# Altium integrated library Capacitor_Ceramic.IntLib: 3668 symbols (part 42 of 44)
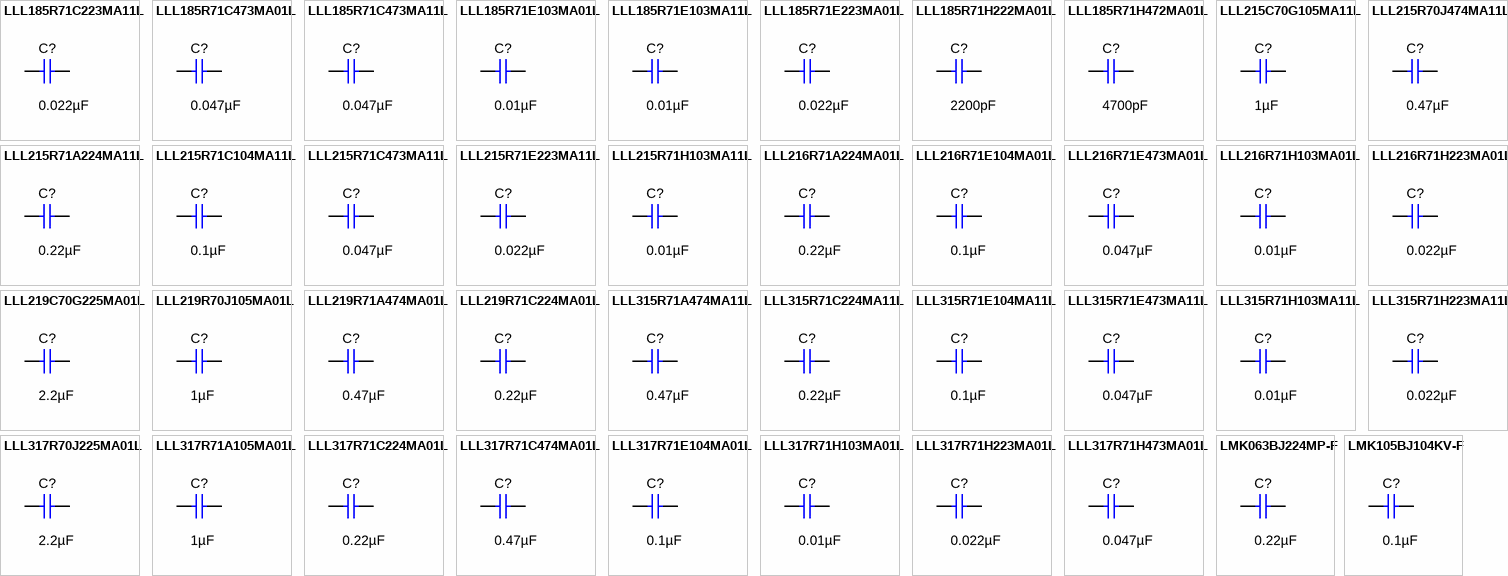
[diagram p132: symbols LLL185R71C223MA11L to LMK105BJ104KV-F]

## LLL216R71A224MA01L
designator C?  ValueDisplayed: 0.22µF  (hidden comment: LLL216R71A224MA01L)
CAP, CERM, 0.22 µF, 10 V,+/- 20%, X7R, 0508; Manufacturer: MuRata; Polarized: N; CompType: Capacitor; Value: 0.22uF; U/M: EA; Cap_F: 0.00000022; Tolerance_%: 20; VDC_V: 10; Value2: 10V; TaMin_C: -55; TaMax_C: 125; Cap_Case: 0508; SizeArea_mm2: 2.5; SizeAreaWB_mm2: 6.75; SizeX_mm: 1.25; SizeY_mm: 2; SizeZ_mm: 1; AEC Category: Q200
signal-integrity model Cap
simulation model Cap
footprint 0508
pins: 1, 2

## LLL216R71E104MA01L
designator C?  ValueDisplayed: 0.1µF  (hidden comment: LLL216R71E104MA01L)
CAP, CERM, 0.1 µF, 25 V,+/- 20%, X7R, 0508; Manufacturer: MuRata; Polarized: N; CompType: Capacitor; Value: 0.1uF; U/M: EA; Cap_F: 0.0000001; Tolerance_%: 20; VDC_V: 25; Value2: 25V; TaMin_C: -55; TaMax_C: 125; Cap_Case: 0508; SizeArea_mm2: 2.5; SizeAreaWB_mm2: 6.75; SizeX_mm: 1.25; SizeY_mm: 2; SizeZ_mm: 1; AEC Category: Q200
signal-integrity model Cap
simulation model Cap
footprint 0508
pins: 1, 2

## LLL216R71E473MA01L
designator C?  ValueDisplayed: 0.047µF  (hidden comment: LLL216R71E473MA01L)
CAP, CERM, 0.047 µF, 25 V,+/- 20%, X7R, 0508; Manufacturer: MuRata; Polarized: N; CompType: Capacitor; Value: 0.047uF; U/M: EA; Cap_F: 0.000000047; Tolerance_%: 20; VDC_V: 25; Value2: 25V; TaMin_C: -55; TaMax_C: 125; Cap_Case: 0508; SizeArea_mm2: 2.5; SizeAreaWB_mm2: 6.75; SizeX_mm: 1.25; SizeY_mm: 2; SizeZ_mm: 1; AEC Category: Q200
signal-integrity model Cap
simulation model Cap
footprint 0508
pins: 1, 2

## LLL216R71H103MA01L
designator C?  ValueDisplayed: 0.01µF  (hidden comment: LLL216R71H103MA01L)
CAP, CERM, 0.01 µF, 50 V,+/- 20%, X7R, 0508; Manufacturer: MuRata; Polarized: N; CompType: Capacitor; Value: 0.01uF; U/M: EA; Cap_F: 0.00000001; Tolerance_%: 20; VDC_V: 50; Value2: 50V; TaMin_C: -55; TaMax_C: 125; Cap_Case: 0508; SizeArea_mm2: 2.5; SizeAreaWB_mm2: 6.75; SizeX_mm: 1.25; SizeY_mm: 2; SizeZ_mm: 1; AEC Category: Q200
signal-integrity model Cap
simulation model Cap
footprint 0508
pins: 1, 2

## LLL216R71H223MA01L
designator C?  ValueDisplayed: 0.022µF  (hidden comment: LLL216R71H223MA01L)
CAP, CERM, 0.022 µF, 50 V,+/- 20%, X7R, 0508; Manufacturer: MuRata; Polarized: N; CompType: Capacitor; Value: 0.022uF; U/M: EA; Cap_F: 0.000000022; Tolerance_%: 20; VDC_V: 50; Value2: 50V; TaMin_C: -55; TaMax_C: 125; Cap_Case: 0508; SizeArea_mm2: 2.5; SizeAreaWB_mm2: 6.75; SizeX_mm: 1.25; SizeY_mm: 2; SizeZ_mm: 1; AEC Category: Q200
signal-integrity model Cap
simulation model Cap
footprint 0508
pins: 1, 2

## LLL219C70G225MA01L
designator C?  ValueDisplayed: 2.2µF  (hidden comment: LLL219C70G225MA01L)
CAP, CERM, 2.2 µF, 4 V,+/- 20%, X7S, 0508; Manufacturer: MuRata; Polarized: N; CompType: Capacitor; Value: 2.2uF; U/M: EA; Cap_F: 0.0000022; Tolerance_%: 20; VDC_V: 4; Value2: 4V; TaMin_C: -55; TaMax_C: 125; Cap_Case: 0508; SizeArea_mm2: 2.5; SizeAreaWB_mm2: 6.75; SizeX_mm: 1.25; SizeY_mm: 2; SizeZ_mm: 1; AEC Category: Q200
signal-integrity model Cap
simulation model Cap
footprint 0508
pins: 1, 2

## LLL219R70J105MA01L
designator C?  ValueDisplayed: 1µF  (hidden comment: LLL219R70J105MA01L)
CAP, CERM, 1 µF, 6.3 V,+/- 20%, X7R, 0508; Manufacturer: MuRata; Polarized: N; CompType: Capacitor; Value: 1uF; U/M: EA; Cap_F: 0.000001; Tolerance_%: 20; VDC_V: 6.3; Value2: 6.3V; TaMin_C: -55; TaMax_C: 125; Cap_Case: 0508; SizeArea_mm2: 2.5; SizeAreaWB_mm2: 6.75; SizeX_mm: 1.25; SizeY_mm: 2; SizeZ_mm: 1; AEC Category: Q200
signal-integrity model Cap
simulation model Cap
footprint 0508
pins: 1, 2

## LLL219R71A474MA01L
designator C?  ValueDisplayed: 0.47µF  (hidden comment: LLL219R71A474MA01L)
CAP, CERM, 0.47 µF, 10 V,+/- 20%, X7R, 0508; Manufacturer: MuRata; Polarized: N; CompType: Capacitor; Value: 0.47uF; U/M: EA; Cap_F: 0.00000047; Tolerance_%: 20; VDC_V: 10; Value2: 10V; TaMin_C: -55; TaMax_C: 125; Cap_Case: 0508; SizeArea_mm2: 2.5; SizeAreaWB_mm2: 6.75; SizeX_mm: 1.25; SizeY_mm: 2; SizeZ_mm: 1; AEC Category: Q200
signal-integrity model Cap
simulation model Cap
footprint 0508
pins: 1, 2

## LLL219R71C224MA01L
designator C?  ValueDisplayed: 0.22µF  (hidden comment: LLL219R71C224MA01L)
CAP, CERM, 0.22 µF, 16 V,+/- 20%, X7R, 0508; Manufacturer: MuRata; Polarized: N; CompType: Capacitor; Value: 0.22uF; U/M: EA; Cap_F: 0.00000022; Tolerance_%: 20; VDC_V: 16; Value2: 16V; TaMin_C: -55; TaMax_C: 125; Cap_Case: 0508; SizeArea_mm2: 2.5; SizeAreaWB_mm2: 6.75; SizeX_mm: 1.25; SizeY_mm: 2; SizeZ_mm: 1; AEC Category: Q200
signal-integrity model Cap
simulation model Cap
footprint 0508
pins: 1, 2

## LLL315R71A474MA11L
designator C?  ValueDisplayed: 0.47µF  (hidden comment: LLL315R71A474MA11L)
CAP, CERM, 0.47 µF, 10 V,+/- 20%, X7R, 0612; Manufacturer: MuRata; Polarized: N; CompType: Capacitor; Value: 0.47uF; U/M: EA; Cap_F: 0.00000047; Tolerance_%: 20; VDC_V: 10; Value2: 10V; TaMin_C: -55; TaMax_C: 125; Cap_Case: 0612; SizeArea_mm2: 5.12; SizeAreaWB_mm2: 10.92; SizeX_mm: 1.6; SizeY_mm: 3.2; SizeZ_mm: 0.85; AEC Category: Q200
signal-integrity model Cap
simulation model Cap
footprint 0612
pins: 1, 2

## LLL315R71C224MA11L
designator C?  ValueDisplayed: 0.22µF  (hidden comment: LLL315R71C224MA11L)
CAP, CERM, 0.22 µF, 16 V,+/- 20%, X7R, 0612; Manufacturer: MuRata; Polarized: N; CompType: Capacitor; Value: 0.22uF; U/M: EA; Cap_F: 0.00000022; Tolerance_%: 20; VDC_V: 16; Value2: 16V; TaMin_C: -55; TaMax_C: 125; Cap_Case: 0612; SizeArea_mm2: 5.12; SizeAreaWB_mm2: 10.92; SizeX_mm: 1.6; SizeY_mm: 3.2; SizeZ_mm: 0.85; AEC Category: Q200
signal-integrity model Cap
simulation model Cap
footprint 0612
pins: 1, 2

## LLL315R71E104MA11L
designator C?  ValueDisplayed: 0.1µF  (hidden comment: LLL315R71E104MA11L)
CAP, CERM, 0.1 µF, 25 V,+/- 20%, X7R, 0612; Manufacturer: MuRata; Polarized: N; CompType: Capacitor; Value: 0.1uF; U/M: EA; Cap_F: 0.0000001; Tolerance_%: 20; VDC_V: 25; Value2: 25V; TaMin_C: -55; TaMax_C: 125; Cap_Case: 0612; SizeArea_mm2: 5.12; SizeAreaWB_mm2: 10.92; SizeX_mm: 1.6; SizeY_mm: 3.2; SizeZ_mm: 0.85; AEC Category: Q200
signal-integrity model Cap
simulation model Cap
footprint 0612
pins: 1, 2

## LLL315R71E473MA11L
designator C?  ValueDisplayed: 0.047µF  (hidden comment: LLL315R71E473MA11L)
CAP, CERM, 0.047 µF, 25 V,+/- 20%, X7R, 0612; Manufacturer: MuRata; Polarized: N; CompType: Capacitor; Value: 0.047uF; U/M: EA; Cap_F: 0.000000047; Tolerance_%: 20; VDC_V: 25; Value2: 25V; TaMin_C: -55; TaMax_C: 125; Cap_Case: 0612; SizeArea_mm2: 5.12; SizeAreaWB_mm2: 10.92; SizeX_mm: 1.6; SizeY_mm: 3.2; SizeZ_mm: 0.85; AEC Category: Q200
signal-integrity model Cap
simulation model Cap
footprint 0612
pins: 1, 2

## LLL315R71H103MA11L
designator C?  ValueDisplayed: 0.01µF  (hidden comment: LLL315R71H103MA11L)
CAP, CERM, 0.01 µF, 50 V,+/- 20%, X7R, 0612; Manufacturer: MuRata; Polarized: N; CompType: Capacitor; Value: 0.01uF; U/M: EA; Cap_F: 0.00000001; Tolerance_%: 20; VDC_V: 50; Value2: 50V; TaMin_C: -55; TaMax_C: 125; Cap_Case: 0612; SizeArea_mm2: 5.12; SizeAreaWB_mm2: 10.92; SizeX_mm: 1.6; SizeY_mm: 3.2; SizeZ_mm: 0.85; AEC Category: Q200
signal-integrity model Cap
simulation model Cap
footprint 0612
pins: 1, 2

## LLL315R71H223MA11L
designator C?  ValueDisplayed: 0.022µF  (hidden comment: LLL315R71H223MA11L)
CAP, CERM, 0.022 µF, 50 V,+/- 20%, X7R, 0612; Manufacturer: MuRata; Polarized: N; CompType: Capacitor; Value: 0.022uF; U/M: EA; Cap_F: 0.000000022; Tolerance_%: 20; VDC_V: 50; Value2: 50V; TaMin_C: -55; TaMax_C: 125; Cap_Case: 0612; SizeArea_mm2: 5.12; SizeAreaWB_mm2: 10.92; SizeX_mm: 1.6; SizeY_mm: 3.2; SizeZ_mm: 0.85; AEC Category: Q200
signal-integrity model Cap
simulation model Cap
footprint 0612
pins: 1, 2

## LLL317R70J225MA01L
designator C?  ValueDisplayed: 2.2µF  (hidden comment: LLL317R70J225MA01L)
CAP, CERM, 2.2 µF, 6.3 V,+/- 20%, X7R, 0612; Manufacturer: MuRata; Polarized: N; CompType: Capacitor; Value: 2.2uF; U/M: EA; Cap_F: 0.0000022; Tolerance_%: 20; VDC_V: 6.3; Value2: 6.3V; TaMin_C: -55; TaMax_C: 125; Cap_Case: 0612; SizeArea_mm2: 5.12; SizeAreaWB_mm2: 10.92; SizeX_mm: 1.6; SizeY_mm: 3.2; SizeZ_mm: 0.85; AEC Category: Q200
signal-integrity model Cap
simulation model Cap
footprint 0612
pins: 1, 2

## LLL317R71A105MA01L
designator C?  ValueDisplayed: 1µF  (hidden comment: LLL317R71A105MA01L)
CAP, CERM, 1 µF, 10 V,+/- 20%, X7R, 0612; Manufacturer: MuRata; Polarized: N; CompType: Capacitor; Value: 1uF; U/M: EA; Cap_F: 0.000001; Tolerance_%: 20; VDC_V: 10; Value2: 10V; TaMin_C: -55; TaMax_C: 125; Cap_Case: 0612; SizeArea_mm2: 5.12; SizeAreaWB_mm2: 10.92; SizeX_mm: 1.6; SizeY_mm: 3.2; SizeZ_mm: 0.85; AEC Category: Q200
signal-integrity model Cap
simulation model Cap
footprint 0612
pins: 1, 2

## LLL317R71C224MA01L
designator C?  ValueDisplayed: 0.22µF  (hidden comment: LLL317R71C224MA01L)
CAP, CERM, 0.22 µF, 16 V,+/- 20%, X7R, 0612; Manufacturer: MuRata; Polarized: N; CompType: Capacitor; Value: 0.22uF; U/M: EA; Cap_F: 0.00000022; Tolerance_%: 20; VDC_V: 16; Value2: 16V; TaMin_C: -55; TaMax_C: 125; Cap_Case: 0612; SizeArea_mm2: 5.12; SizeAreaWB_mm2: 10.92; SizeX_mm: 1.6; SizeY_mm: 3.2; SizeZ_mm: 0.85; AEC Category: Q200
signal-integrity model Cap
simulation model Cap
footprint 0612
pins: 1, 2

## LLL317R71C474MA01L
designator C?  ValueDisplayed: 0.47µF  (hidden comment: LLL317R71C474MA01L)
CAP, CERM, 0.47 µF, 16 V,+/- 20%, X7R, 0612; Manufacturer: MuRata; Polarized: N; CompType: Capacitor; Value: 0.47uF; U/M: EA; Cap_F: 0.00000047; Tolerance_%: 20; VDC_V: 16; Value2: 16V; TaMin_C: -55; TaMax_C: 125; Cap_Case: 0612; SizeArea_mm2: 5.12; SizeAreaWB_mm2: 10.92; SizeX_mm: 1.6; SizeY_mm: 3.2; SizeZ_mm: 0.85; AEC Category: Q200
signal-integrity model Cap
simulation model Cap
footprint 0612
pins: 1, 2

## LLL317R71E104MA01L
designator C?  ValueDisplayed: 0.1µF  (hidden comment: LLL317R71E104MA01L)
CAP, CERM, 0.1 µF, 25 V,+/- 20%, X7R, 0612; Manufacturer: MuRata; Polarized: N; CompType: Capacitor; Value: 0.1uF; U/M: EA; Cap_F: 0.0000001; Tolerance_%: 20; VDC_V: 25; Value2: 25V; TaMin_C: -55; TaMax_C: 125; Cap_Case: 0612; SizeArea_mm2: 5.12; SizeAreaWB_mm2: 10.92; SizeX_mm: 1.6; SizeY_mm: 3.2; SizeZ_mm: 0.85; AEC Category: Q200
signal-integrity model Cap
simulation model Cap
footprint 0612
pins: 1, 2

## LLL317R71H103MA01L
designator C?  ValueDisplayed: 0.01µF  (hidden comment: LLL317R71H103MA01L)
CAP, CERM, 0.01 µF, 50 V,+/- 20%, X7R, 0612; Manufacturer: MuRata; Polarized: N; CompType: Capacitor; Value: 0.01uF; U/M: EA; Cap_F: 0.00000001; Tolerance_%: 20; VDC_V: 50; Value2: 50V; TaMin_C: -55; TaMax_C: 125; Cap_Case: 0612; SizeArea_mm2: 5.12; SizeAreaWB_mm2: 10.92; SizeX_mm: 1.6; SizeY_mm: 3.2; SizeZ_mm: 0.85; AEC Category: Q200
signal-integrity model Cap
simulation model Cap
footprint 0612
pins: 1, 2

## LLL317R71H223MA01L
designator C?  ValueDisplayed: 0.022µF  (hidden comment: LLL317R71H223MA01L)
CAP, CERM, 0.022 µF, 50 V,+/- 20%, X7R, 0612; Manufacturer: MuRata; Polarized: N; CompType: Capacitor; Value: 0.022uF; U/M: EA; Cap_F: 0.000000022; Tolerance_%: 20; VDC_V: 50; Value2: 50V; TaMin_C: -55; TaMax_C: 125; Cap_Case: 0612; SizeArea_mm2: 5.12; SizeAreaWB_mm2: 10.92; SizeX_mm: 1.6; SizeY_mm: 3.2; SizeZ_mm: 0.85; AEC Category: Q200
signal-integrity model Cap
simulation model Cap
footprint 0612
pins: 1, 2

## LLL317R71H473MA01L
designator C?  ValueDisplayed: 0.047µF  (hidden comment: LLL317R71H473MA01L)
CAP, CERM, 0.047 µF, 50 V,+/- 20%, X7R, 0612; Manufacturer: MuRata; Polarized: N; CompType: Capacitor; Value: 0.047uF; U/M: EA; Cap_F: 0.000000047; Tolerance_%: 20; VDC_V: 50; Value2: 50V; TaMin_C: -55; TaMax_C: 125; Cap_Case: 0612; SizeArea_mm2: 5.12; SizeAreaWB_mm2: 10.92; SizeX_mm: 1.6; SizeY_mm: 3.2; SizeZ_mm: 0.85; AEC Category: Q200
signal-integrity model Cap
simulation model Cap
footprint 0612
pins: 1, 2

## LMK063BJ224MP-F
designator C?  ValueDisplayed: 0.22µF  (hidden comment: LMK063BJ224MP-F)
CAP, CERM, 0.22 µF, 10 V,+/- 20%, X5R, 0201; Manufacturer: Taiyo Yuden; Polarized: N; CompType: Capacitor; Value: 0.22uF; U/M: EA; Cap_F: 0.00000022; Tolerance_%: 20; VDC_V: 10; Value2: 10V; TaMin_C: -55; TaMax_C: 85; Cap_Case: 0201; SizeArea_mm2: 0.18; SizeAreaWB_mm2: 2.08; SizeX_mm: 0.6; SizeY_mm: 0.3; SizeZ_mm: 0.33; AEC Category: Q200; Green_Lifecycle: Active; Green_REACh: Passed
signal-integrity model Cap
simulation model Cap
footprint 0201_033
footprint 0201_033M
footprint 0201_033L
pins: 1, 2

## LMK105BJ104KV-F
designator C?  ValueDisplayed: 0.1µF  (hidden comment: LMK105BJ104KV-F)
CAP, CERM, 0.1 µF, 10 V,+/- 10%, X5R, 0402; Manufacturer: Taiyo Yuden; Polarized: N; CompType: Capacitor; Value: 0.1uF; U/M: EA; Cap_F: 0.0000001; Tolerance_%: 10; Value2: 10V; TaMin_C: -55; TaMax_C: 85; Cap_Case: 0402; SizeArea_mm2: 0.5; SizeAreaWB_mm2: 3; SizeX_mm: 1; SizeZ_mm: 0.6; AEC Category: Q200; Green_Lifecycle: Active; Green_REACh: Passed
signal-integrity model Cap
simulation model Cap
footprint 0402
footprint 0402M
footprint 0402L
footprint 0402S
pins: 1, 2

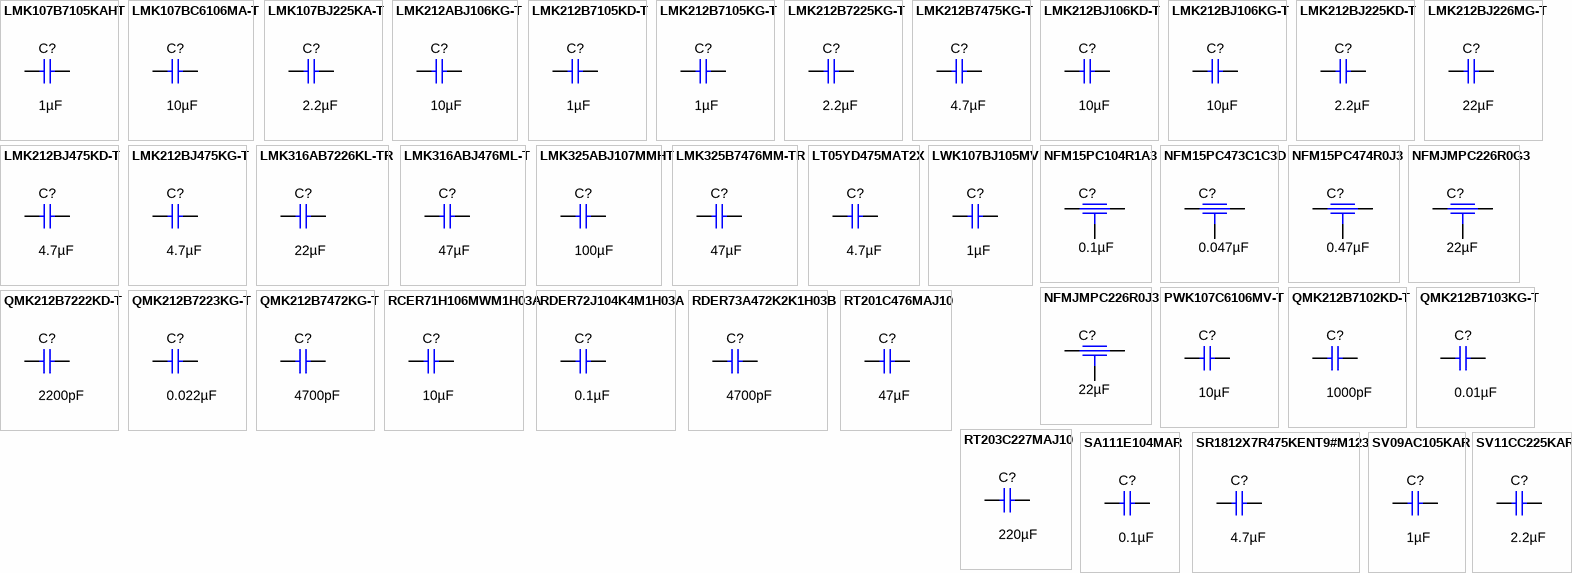
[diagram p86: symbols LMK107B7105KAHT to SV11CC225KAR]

## LMK107B7105KAHT
designator C?  ValueDisplayed: 1µF  (hidden comment: LMK107B7105KAHT)
CAP, CERM, 1 µF, 10 V,+/- 10%, X7R, AEC-Q200 Grade 1, 0603; Manufacturer: Taiyo Yuden; Polarized: N; CompType: Capacitor; Value: 1uF; U/M: EA; Cap_F: 0.000001; Tolerance_%: 10; Value2: 10V; TaMin_C: -55; TaMax_C: 125; Cap_Case: 0603; SizeArea_mm2: 1.28; SizeAreaWB_mm2: 4.68; SizeX_mm: 1.6; SizeY_mm: 0.8; SizeZ_mm: 1; AEC Category: Q200; AEC Qualified: Y
signal-integrity model Cap
simulation model Cap
footprint 0603
footprint 0603M
footprint 0603L
footprint 0603_HV
footprint 0603S
pins: 1, 2

## LMK107BC6106MA-T
designator C?  ValueDisplayed: 10µF  (hidden comment: LMK107BC6106MA-T)
CAP, CERM, 10 µF, 10 V,+/- 20%, X6S, 0603; Manufacturer: Taiyo Yuden; Polarized: N; CompType: Capacitor; Value: 10uF; U/M: EA; Cap_F: 0.00001; Tolerance_%: 20; VDC_V: 10; Value2: 10V; TaMin_C: -55; TaMax_C: 105; Cap_Case: 0603; SizeArea_mm2: 1.28; SizeAreaWB_mm2: 4.68; SizeX_mm: 1.6; SizeY_mm: 0.8; SizeZ_mm: 1; AEC Category: Q200
signal-integrity model Cap
simulation model Cap
footprint 0603
footprint 0603M
footprint 0603L
footprint 0603_HV
footprint 0603S
pins: 1, 2

## LMK107BJ225KA-T
designator C?  ValueDisplayed: 2.2µF  (hidden comment: LMK107BJ225KA-T)
CAP, CERM, 2.2 µF, 10 V,+/- 10%, X5R, 0603; Manufacturer: Taiyo Yuden; Polarized: N; CompType: Capacitor; Value: 2.2uF; U/M: EA; Cap_F: 0.0000022; Tolerance_%: 10; Value2: 10V; TaMin_C: -55; TaMax_C: 85; Cap_Case: 0603; SizeArea_mm2: 1.28; SizeAreaWB_mm2: 4.68; SizeX_mm: 1.6; SizeY_mm: 0.8; SizeZ_mm: 1; AEC Category: Q200; Green_Lifecycle: Active; Green_REACh: Passed
signal-integrity model Cap
simulation model Cap
footprint 0603
footprint 0603M
footprint 0603L
footprint 0603_HV
footprint 0603S
pins: 1, 2

## LMK212ABJ106KG-T
designator C?  ValueDisplayed: 10µF  (hidden comment: LMK212ABJ106KG-T)
CAP, CERM, 10 µF, 10 V,+/- 10%, X5R, 0805; Manufacturer: Taiyo Yuden; Polarized: N; CompType: Capacitor; Value: 10uF; U/M: EA; Cap_F: 0.00001; Tolerance_%: 10; Value2: 10V; TaMin_C: -55; TaMax_C: 85; Cap_Case: 0805; SizeArea_mm2: 2.5; SizeAreaWB_mm2: 6.75; SizeX_mm: 2; SizeY_mm: 1.25; SizeZ_mm: 1.45; AEC Category: Q200
signal-integrity model Cap
simulation model Cap
footprint 0805_HV
footprint 0805_HV1
footprint 0805
footprint 0805M
footprint 0805L
pins: 1, 2

## LMK212B7105KD-T
designator C?  ValueDisplayed: 1µF  (hidden comment: LMK212B7105KD-T)
CAP, CERM, 1 µF, 10 V,+/- 10%, X7R, 0805; Manufacturer: Taiyo Yuden; Polarized: N; CompType: Capacitor; Value: 1uF; U/M: EA; Cap_F: 0.000001; Tolerance_%: 10; Value2: 10V; TaMin_C: -55; TaMax_C: 125; Cap_Case: 0805; SizeArea_mm2: 2.5; SizeAreaWB_mm2: 6.75; SizeX_mm: 2; SizeY_mm: 1.25; SizeZ_mm: 1.45; AEC Category: Q200
signal-integrity model Cap
simulation model Cap
footprint 0805_HV
footprint 0805_HV1
footprint 0805
footprint 0805M
footprint 0805L
pins: 1, 2

## LMK212B7105KG-T
designator C?  ValueDisplayed: 1µF  (hidden comment: LMK212B7105KG-T)
CAP, CERM, 1 µF, 10 V,+/- 10%, X7R, 0805; Manufacturer: Taiyo Yuden; Polarized: N; CompType: Capacitor; Value: 1uF; U/M: EA; Cap_F: 0.000001; Tolerance_%: 10; Value2: 10V; TaMin_C: -55; TaMax_C: 125; Cap_Case: 0805; SizeArea_mm2: 2.5; SizeAreaWB_mm2: 6.75; SizeX_mm: 2; SizeY_mm: 1.25; SizeZ_mm: 1.45; AEC Category: Q200
signal-integrity model Cap
simulation model Cap
footprint 0805_HV
footprint 0805_HV1
footprint 0805
footprint 0805M
footprint 0805L
pins: 1, 2

## LMK212B7225KG-T
designator C?  ValueDisplayed: 2.2µF  (hidden comment: LMK212B7225KG-T)
CAP, CERM, 2.2 µF, 10 V,+/- 10%, X7R, 0805; Manufacturer: Taiyo Yuden; Polarized: N; CompType: Capacitor; Value: 2.2uF; U/M: EA; Cap_F: 0.0000022; Tolerance_%: 10; Value2: 10V; TaMin_C: -55; TaMax_C: 125; Cap_Case: 0805; SizeArea_mm2: 2.5; SizeAreaWB_mm2: 6.75; SizeX_mm: 2; SizeY_mm: 1.25; SizeZ_mm: 1.45; AEC Category: Q200; Green_Lifecycle: Active; Green_REACh: Passed
signal-integrity model Cap
simulation model Cap
footprint 0805_HV
footprint 0805_HV1
footprint 0805
footprint 0805M
footprint 0805L
pins: 1, 2

## LMK212B7475KG-T
designator C?  ValueDisplayed: 4.7µF  (hidden comment: LMK212B7475KG-T)
CAP, CERM, 4.7 µF, 10 V,+/- 10%, X7R, 0805; Manufacturer: Taiyo Yuden; Polarized: N; CompType: Capacitor; Value: 4.7uF; U/M: EA; Cap_F: 0.0000047; Tolerance_%: 10; Value2: 10V; TaMin_C: -55; TaMax_C: 125; Cap_Case: 0805; SizeArea_mm2: 2.5; SizeAreaWB_mm2: 6.75; SizeX_mm: 2; SizeY_mm: 1.25; SizeZ_mm: 1.45; AEC Category: Q200; Green_Lifecycle: Active; Green_REACh: Passed
signal-integrity model Cap
simulation model Cap
footprint 0805_HV
footprint 0805_HV1
footprint 0805
footprint 0805M
footprint 0805L
pins: 1, 2

## LMK212BJ106KD-T
designator C?  ValueDisplayed: 10µF  (hidden comment: LMK212BJ106KD-T)
CAP, CERM, 10 µF, 10 V,+/- 10%, X5R, 0805; Manufacturer: Taiyo Yuden; Polarized: N; CompType: Capacitor; Value: 10uF; U/M: EA; Cap_F: 0.00001; Tolerance_%: 10; ESR_ohm: 0.01; Value1: 0.01 ohm; Value2: 10V; TaMin_C: -55; TaMax_C: 85; Cap_Case: 0805; SizeArea_mm2: 2.5; SizeAreaWB_mm2: 6.75; SizeX_mm: 2; SizeY_mm: 1.25; SizeZ_mm: 1.45; AEC Category: Q200; Green_Lifecycle: Not Set; Green_REACh: Incomplete
signal-integrity model Cap
simulation model Cap
footprint 0805_HV
footprint 0805_HV1
footprint 0805
footprint 0805M
footprint 0805L
pins: 1, 2

## LMK212BJ106KG-T
designator C?  ValueDisplayed: 10µF  (hidden comment: LMK212BJ106KG-T)
CAP, CERM, 10 µF, 10 V,+/- 10%, X5R, 0805; Manufacturer: Taiyo Yuden; Polarized: N; CompType: Capacitor; Value: 10uF; U/M: EA; Cap_F: 0.00001; Tolerance_%: 10; Value2: 10V; TaMin_C: -55; TaMax_C: 85; Cap_Case: 0805; SizeArea_mm2: 2.5; SizeAreaWB_mm2: 6.75; SizeX_mm: 2; SizeY_mm: 1.25; SizeZ_mm: 1.45; AEC Category: Q200; Green_Lifecycle: Not Set; Green_REACh: Incomplete
signal-integrity model Cap
simulation model Cap
footprint 0805_HV
footprint 0805_HV1
footprint 0805
footprint 0805M
footprint 0805L
pins: 1, 2

## LMK212BJ225KD-T
designator C?  ValueDisplayed: 2.2µF  (hidden comment: LMK212BJ225KD-T)
CAP, CERM, 2.2 µF, 10 V,+/- 10%, X5R, 0805; Manufacturer: Taiyo Yuden; Polarized: N; CompType: Capacitor; Value: 2.2uF; U/M: EA; Cap_F: 0.0000022; Tolerance_%: 10; Value2: 10V; TaMin_C: -55; TaMax_C: 85; Cap_Case: 0805; SizeArea_mm2: 2.5; SizeAreaWB_mm2: 6.75; SizeX_mm: 2; SizeY_mm: 1.25; SizeZ_mm: 1.45; AEC Category: Q200
signal-integrity model Cap
simulation model Cap
footprint 0805_HV
footprint 0805_HV1
footprint 0805
footprint 0805M
footprint 0805L
pins: 1, 2

## LMK212BJ226MG-T
designator C?  ValueDisplayed: 22µF  (hidden comment: LMK212BJ226MG-T)
CAP, CERM, 22 µF, 10 V,+/- 20%, X5R, 0805; Manufacturer: Taiyo Yuden; Polarized: N; CompType: Capacitor; Value: 22uF; U/M: EA; Cap_F: 0.000022; Tolerance_%: 20; VDC_V: 10; Value2: 10V; TaMin_C: -55; TaMax_C: 85; Cap_Case: 0805; SizeArea_mm2: 2.5; SizeAreaWB_mm2: 6.75; SizeX_mm: 2; SizeY_mm: 1.25; SizeZ_mm: 1.45; AEC Category: Q200; Green_Lifecycle: Not Set; Green_REACh: Incomplete
signal-integrity model Cap
simulation model Cap
footprint 0805_HV
footprint 0805_HV1
footprint 0805
footprint 0805M
footprint 0805L
pins: 1, 2

## LMK212BJ475KD-T
designator C?  ValueDisplayed: 4.7µF  (hidden comment: LMK212BJ475KD-T)
CAP, CERM, 4.7 µF, 10 V,+/- 10%, X5R, 0805; Manufacturer: Taiyo Yuden; Polarized: N; CompType: Capacitor; Value: 4.7uF; U/M: EA; Cap_F: 0.0000047; Tolerance_%: 10; Value2: 10V; TaMin_C: -55; TaMax_C: 85; Cap_Case: 0805; SizeArea_mm2: 2.5; SizeAreaWB_mm2: 6.75; SizeX_mm: 2; SizeY_mm: 1.25; SizeZ_mm: 1.45; AEC Category: Q200; Green_Lifecycle: Not Set; Green_REACh: Incomplete
signal-integrity model Cap
simulation model Cap
footprint 0805_HV
footprint 0805_HV1
footprint 0805
footprint 0805M
footprint 0805L
pins: 1, 2

## LMK212BJ475KG-T
designator C?  ValueDisplayed: 4.7µF  (hidden comment: LMK212BJ475KG-T)
CAP, CERM, 4.7 µF, 10 V,+/- 10%, X5R, 0805; Manufacturer: Taiyo Yuden; Polarized: N; CompType: Capacitor; Value: 4.7uF; U/M: EA; Cap_F: 0.0000047; Tolerance_%: 10; Value2: 10V; TaMin_C: -55; TaMax_C: 85; Cap_Case: 0805; SizeArea_mm2: 2.5; SizeAreaWB_mm2: 6.75; SizeX_mm: 2; SizeY_mm: 1.25; SizeZ_mm: 1.45; AEC Category: Q200; Green_Lifecycle: Not Set; Green_REACh: Incomplete
signal-integrity model Cap
simulation model Cap
footprint 0805_HV
footprint 0805_HV1
footprint 0805
footprint 0805M
footprint 0805L
pins: 1, 2

## LMK316AB7226KL-TR
designator C?  ValueDisplayed: 22µF  (hidden comment: LMK316AB7226KL-TR)
CAP, CERM, 22 µF, 10 V,+/- 10%, X7R, 1206; Manufacturer: Taiyo Yuden; Polarized: N; CompType: Capacitor; Value: 22uF; U/M: EA; Cap_F: 0.000022; Tolerance_%: 10; Value2: 10V; TaMin_C: -55; TaMax_C: 125; Cap_Case: 1206; SizeArea_mm2: 5.12; SizeAreaWB_mm2: 10.92; SizeX_mm: 3.2; SizeY_mm: 1.6; SizeZ_mm: 1.8; AEC Category: Q200
signal-integrity model Cap
simulation model Cap
footprint 1206_180
footprint 1206_180M
footprint 1206_180L
pins: 1, 2

## LMK316ABJ476ML-T
designator C?  ValueDisplayed: 47µF  (hidden comment: LMK316ABJ476ML-T)
CAP, CERM, 47 µF, 10 V,+/- 20%, X5R, 1206; Manufacturer: Taiyo Yuden; Polarized: N; CompType: Capacitor; Value: 47uF; U/M: EA; Cap_F: 0.000047; Tolerance_%: 20; VDC_V: 10; Value2: 10V; TaMin_C: -55; TaMax_C: 85; Cap_Case: 1206; SizeArea_mm2: 5.12; SizeAreaWB_mm2: 10.92; SizeX_mm: 3.2; SizeY_mm: 1.6; SizeZ_mm: 1.9; AEC Category: Q200
signal-integrity model Cap
simulation model Cap
footprint 1206_190
footprint 1206_190M
footprint 1206_190L
pins: 1, 2

## LMK325ABJ107MMHT
designator C?  ValueDisplayed: 100µF  (hidden comment: LMK325ABJ107MMHT)
CAP, CERM, 100 µF, 10 V,+/- 20%, X5R, AEC-Q200 Grade 3, 1210; Manufacturer: Taiyo Yuden; Polarized: N; CompType: Capacitor; Value: 100uF; U/M: EA; Cap_F: 0.0001; Tolerance_%: 20; VDC_V: 10; Value2: 10V; TaMin_C: -55; TaMax_C: 85; Cap_Case: 1210; SizeArea_mm2: 8; SizeAreaWB_mm2: 14.7; SizeX_mm: 3.2; SizeY_mm: 2.5; SizeZ_mm: 2.8; AEC Category: Q200; AEC Qualified: Y; AEC Grade: 3
signal-integrity model Cap
simulation model Cap
footprint 1210_280
pins: 1, 2

## LMK325B7476MM-TR
designator C?  ValueDisplayed: 47µF  (hidden comment: LMK325B7476MM-TR)
CAP, CERM, 47 µF, 10 V,+/- 20%, X7R, 1210; Manufacturer: Taiyo Yuden; Polarized: N; CompType: Capacitor; Value: 47uF; U/M: EA; Cap_F: 0.000047; Tolerance_%: 20; VDC_V: 10; Value2: 10V; TaMin_C: -55; TaMax_C: 125; Cap_Case: 1210; SizeArea_mm2: 8; SizeAreaWB_mm2: 14.7; SizeX_mm: 3.2; SizeY_mm: 2.5; SizeZ_mm: 2.7; AEC Category: Q200
signal-integrity model Cap
simulation model Cap
footprint 1210_270
footprint 1210_270M
footprint 1210_270L
pins: 1, 2

## LT05YD475MAT2X
designator C?  ValueDisplayed: 4.7µF  (hidden comment: LT05YD475MAT2X)
CAP, CERM, 4.7 µF, 16 V,+/- 20%, X5R, 0805; Manufacturer: AVX; Polarized: N; CompType: Capacitor; Value: 4.7uF; U/M: EA; Cap_F: 0.0000047; Tolerance_%: 20; ESR_ohm: 0.007; Value1: 0.007 ohm; VDC_V: 16; Value2: 16V; TaMin_C: -55; TaMax_C: 85; Cap_Case: 0805; SizeArea_mm2: 2.5; SizeAreaWB_mm2: 6.75; SizeX_mm: 2; SizeY_mm: 1.25; SizeZ_mm: 1.45; AEC Category: Q200
signal-integrity model Cap
simulation model Cap
footprint 0805_HV
footprint 0805_HV1
footprint 0805
footprint 0805M
footprint 0805L
pins: 1, 2

## LWK107BJ105MV
designator C?  ValueDisplayed: 1µF  (hidden comment: LWK107BJ105MV)
CAP, CERM, 1 µF, 10 V,+/- 20%, X5R, 0306; Manufacturer: Taiyo Yuden; Polarized: N; CompType: Capacitor; Value: 1uF; U/M: EA; Cap_F: 0.000001; Tolerance_%: 20; VDC_V: 10; Value2: 10V; TaMin_C: -55; TaMax_C: 85; Cap_Case: 0306; SizeArea_mm2: 1.28; SizeAreaWB_mm2: 4.68; SizeX_mm: 0.8; SizeY_mm: 1.6; SizeZ_mm: 0.6; AEC Category: Q200; Green_Lifecycle: Active; Green_REACh: Passed
signal-integrity model Cap
simulation model Cap
footprint 0306
pins: 1, 2

## NFM15PC104R1A3
designator C?  ValueDisplayed: 0.1µF  (hidden comment: NFM15PC104R1A3)
CAP, CERM, 0.1 µF, 10 V,+/- 20%, 1x0.5mm; Manufacturer: MuRata; SymbolCreator: a0411947; CompType: Capacitor; U/M: EA; Cap_F: 0.0000001; Value: 0.1uF; Tolerance_%: 20; VDC_V: 10; Value2: 10V; TempCo: Unknown; TaMin_C: -55; TaMax_C: 105; Polarized: N; Cap_Case: 0402; SizeArea_mm2: 0.5; SizeAreaWB_mm2: 3; SizeX_mm: 1; AEC Category: Q200
footprint NFM15PC
pins: 1, 2, 3

## NFM15PC473C1C3D
designator C?  ValueDisplayed: 0.047µF  (hidden comment: NFM15PC473C1C3D)
CAP, CERM, 0.047 µF, 16 V,+/- 20%, 1x0.5mm; Manufacturer: MuRata; SymbolCreator: a0411947; CompType: Capacitor; U/M: EA; Cap_F: 0.000000047; Value: 0.047uF; Tolerance_%: 20; VDC_V: 16; Value2: 16V; TempCo: Unknown; TaMin_C: -55; TaMax_C: 105; Polarized: N; Cap_Case: 0402; SizeArea_mm2: 0.5; SizeAreaWB_mm2: 3; SizeX_mm: 1; AEC Category: Q200
footprint NFM15PC
pins: 1, 2, 3

## NFM15PC474R0J3
designator C?  ValueDisplayed: 0.47µF  (hidden comment: NFM15PC474R0J3)
CAP, CERM, 0.47 µF, 6.3 V,+/- 20%, 1x0.5mm; Manufacturer: MuRata; SymbolCreator: a0411947; CompType: Capacitor; U/M: EA; Cap_F: 0.00000047; Value: 0.47uF; Tolerance_%: 20; VDC_V: 6.3; Value2: 6.3V; TempCo: Unknown; TaMin_C: -55; TaMax_C: 85; Polarized: N; Cap_Case: 0402; SizeArea_mm2: 0.5; SizeAreaWB_mm2: 3; SizeX_mm: 1; SizeZ_mm: 0.35; AEC Category: Q200
footprint NFM15PCC
pins: 1, 2, 3

## NFMJMPC226R0G3
designator C?  ValueDisplayed: 22µF  (hidden comment: NFMJMPC226R0G3)
CAP, CERM, 22 µF, 4 V,+/- 20%, 1.2x0.9mm; Manufacturer: MuRata; SymbolCreator: a0411947; CompType: Capacitor; U/M: EA; Cap_F: 0.000022; Value: 22uF; Tolerance_%: 20; VDC_V: 4; Value2: 4V; TempCo: Unknown; TaMin_C: -55; TaMax_C: 85; Polarized: N; SizeArea_mm2: 1.08; SizeAreaWB_mm2: 4.18; SizeX_mm: 1.2; SizeY_mm: 0.9; SizeZ_mm: 0.8; AEC Category: Q200
footprint Murata_NFMJMPC
pins: 1, 2, 3

## NFMJMPC226R0J3
designator C?  ValueDisplayed: 22µF  (hidden comment: NFMJMPC226R0J3)
CAP, CERM, 22 µF, 6.3 V,+/- 20%, 1.2x0.9mm; Manufacturer: MuRata; SymbolCreator: a0411947; CompType: Capacitor; U/M: EA; Cap_F: 0.000022; Value: 22uF; Tolerance_%: 20; VDC_V: 6.3; Value2: 6.3V; TempCo: Unknown; TaMin_C: -55; TaMax_C: 85; Polarized: N; SizeArea_mm2: 1.08; SizeAreaWB_mm2: 4.18; SizeX_mm: 1.2; SizeY_mm: 0.9; SizeZ_mm: 0.8; AEC Category: Q200
footprint Murata_NFMJMPC
pins: 1, 2, 3

## PWK107C6106MV-T
designator C?  ValueDisplayed: 10µF  (hidden comment: PWK107C6106MV-T)
CAP, CERM, 10 µF, 2.5 V,+/- 20%, X6S, 0306; Manufacturer: Taiyo Yuden; Polarized: N; CompType: Capacitor; Value: 10uF; U/M: EA; Cap_F: 0.00001; Tolerance_%: 20; VDC_V: 2.5; Value2: 2.5V; TaMin_C: -55; TaMax_C: 105; Cap_Case: 0306; SizeArea_mm2: 1.28; SizeAreaWB_mm2: 4.68; SizeX_mm: 0.8; SizeY_mm: 1.6; SizeZ_mm: 0.6; AEC Category: Q200
signal-integrity model Cap
simulation model Cap
footprint 0306
pins: 1, 2

## QMK212B7102KD-T
designator C?  ValueDisplayed: 1000pF  (hidden comment: QMK212B7102KD-T)
CAP, CERM, 1000 pF, 250 V,+/- 10%, X7R, 0805; Manufacturer: Taiyo Yuden; Polarized: N; CompType: Capacitor; Value: 1000pF; U/M: EA; Cap_F: 0.000000001; Tolerance_%: 10; VDC_V: 250; Value2: 250V; TaMin_C: -55; TaMax_C: 125; Cap_Case: 0805; SizeArea_mm2: 2.5; SizeAreaWB_mm2: 6.75; SizeX_mm: 2; SizeY_mm: 1.25; SizeZ_mm: 1.45; AEC Category: Q200
signal-integrity model Cap
simulation model Cap
footprint 0805_HV
footprint 0805_HV1
footprint 0805
footprint 0805M
footprint 0805L
pins: 1, 2

## QMK212B7103KG-T
designator C?  ValueDisplayed: 0.01µF  (hidden comment: QMK212B7103KG-T)
CAP, CERM, 0.01 µF, 250 V,+/- 10%, X7R, 0805; Manufacturer: Taiyo Yuden; Polarized: N; CompType: Capacitor; Value: 0.01uF; U/M: EA; Cap_F: 0.00000001; Tolerance_%: 10; VDC_V: 250; Value2: 250V; TaMin_C: -55; TaMax_C: 125; Cap_Case: 0805; SizeArea_mm2: 2.5; SizeAreaWB_mm2: 6.75; SizeX_mm: 2; SizeY_mm: 1.25; SizeZ_mm: 1.45; AEC Category: Q200
signal-integrity model Cap
simulation model Cap
footprint 0805_HV
footprint 0805_HV1
footprint 0805
footprint 0805M
footprint 0805L
pins: 1, 2

## QMK212B7222KD-T
designator C?  ValueDisplayed: 2200pF  (hidden comment: QMK212B7222KD-T)
CAP, CERM, 2200 pF, 250 V,+/- 10%, X7R, 0805; Manufacturer: Taiyo Yuden; Polarized: N; CompType: Capacitor; Value: 2200pF; U/M: EA; Cap_F: 0.0000000022; Tolerance_%: 10; VDC_V: 250; Value2: 250V; TaMin_C: -55; TaMax_C: 125; Cap_Case: 0805; SizeArea_mm2: 2.5; SizeAreaWB_mm2: 6.75; SizeX_mm: 2; SizeY_mm: 1.25; SizeZ_mm: 1.45; AEC Category: Q200
signal-integrity model Cap
simulation model Cap
footprint 0805_HV
footprint 0805_HV1
footprint 0805
footprint 0805M
footprint 0805L
pins: 1, 2

## QMK212B7223KG-T
designator C?  ValueDisplayed: 0.022µF  (hidden comment: QMK212B7223KG-T)
CAP, CERM, 0.022 µF, 250 V,+/- 10%, X7R, 0805; Manufacturer: Taiyo Yuden; Polarized: N; CompType: Capacitor; Value: 0.022uF; U/M: EA; Cap_F: 0.000000022; Tolerance_%: 10; VDC_V: 250; Value2: 250V; TaMin_C: -55; TaMax_C: 125; Cap_Case: 0805; SizeArea_mm2: 2.5; SizeAreaWB_mm2: 6.75; SizeX_mm: 2; SizeY_mm: 1.25; SizeZ_mm: 1.45; AEC Category: Q200
signal-integrity model Cap
simulation model Cap
footprint 0805_HV
footprint 0805_HV1
footprint 0805
footprint 0805M
footprint 0805L
pins: 1, 2

## QMK212B7472KG-T
designator C?  ValueDisplayed: 4700pF  (hidden comment: QMK212B7472KG-T)
CAP, CERM, 4700 pF, 250 V,+/- 10%, X7R, 0805; Manufacturer: Taiyo Yuden; Polarized: N; CompType: Capacitor; Value: 4700pF; U/M: EA; Cap_F: 0.0000000047; Tolerance_%: 10; VDC_V: 250; Value2: 250V; TaMin_C: -55; TaMax_C: 125; Cap_Case: 0805; SizeArea_mm2: 2.5; SizeAreaWB_mm2: 6.75; SizeX_mm: 2; SizeY_mm: 1.25; SizeZ_mm: 1.45; AEC Category: Q200
signal-integrity model Cap
simulation model Cap
footprint 0805_HV
footprint 0805_HV1
footprint 0805
footprint 0805M
footprint 0805L
pins: 1, 2

## RCER71H106MWM1H03A
designator C?  ValueDisplayed: 10µF  (hidden comment: RCER71H106MWM1H03A)
CAP, CERM, 10 µF, 50 V,+/- 20%, X7R, AEC-Q200 Grade 1, 5.5x4mm; Manufacturer: MuRata; Polarized: N; CompType: Capacitor; Value: 10uF; U/M: EA; Cap_F: 0.00001; Tolerance_%: 20; VDC_V: 50; Value2: 50V; TaMin_C: -55; TaMax_C: 125; Cap_Case: 5.5x4x10mm; SizeArea_mm2: 22; SizeAreaWB_mm2: 45; SizeX_mm: 5.5; SizeY_mm: 4; SizeZ_mm: 10; AEC Category: Q200; AEC Qualified: Y; AEC Grade: 1
signal-integrity model Cap
simulation model Cap
footprint RCE_550x400x1000
pins: 1, 2

## RDER72J104K4M1H03A
designator C?  ValueDisplayed: 0.1µF  (hidden comment: RDER72J104K4M1H03A)
CAP, CERM, 0.1 µF, 630 V,+/- 10%, X7R, 7.5x3.15mm; Manufacturer: MuRata; Polarized: N; CompType: Capacitor; Value: 0.1uF; U/M: EA; Cap_F: 0.0000001; Tolerance_%: 10; VDC_V: 630; Value2: 630V; TaMin_C: -55; TaMax_C: 125; Cap_Case: 7.5x3.15x8mm; SizeArea_mm2: 23.625; SizeAreaWB_mm2: 48.925; SizeX_mm: 7.5; SizeY_mm: 3.15; SizeZ_mm: 8; AEC Category: Q200
signal-integrity model Cap
simulation model Cap
footprint RDE_750x315x800
pins: 1, 2

## RDER73A472K2K1H03B
designator C?  ValueDisplayed: 4700pF  (hidden comment: RDER73A472K2K1H03B)
CAP, CERM, 4700 pF, 1000 V,+/- 10%, X7R, 5.5x3.15mm; Manufacturer: MuRata; Polarized: N; CompType: Capacitor; Value: 4700pF; U/M: EA; Cap_F: 0.0000000047; Tolerance_%: 10; VDC_V: 1000; Value2: 1000V; TaMin_C: -55; TaMax_C: 125; Cap_Case: 5.5x3.15x6mm; SizeArea_mm2: 17.325; SizeAreaWB_mm2: 38.625; SizeX_mm: 5.5; SizeY_mm: 3.15; SizeZ_mm: 6; AEC Category: Q200
signal-integrity model Cap
simulation model Cap
footprint RDE_550x315x600
pins: 1, 2

## RT201C476MAJ10
designator C?  ValueDisplayed: 47µF  (hidden comment: RT201C476MAJ10)
CAP, CERM, 47 µF, 100 V,+/- 20%, X7R, 1075x300mil; Manufacturer: AVX; Polarized: N; CompType: Capacitor; Value: 47uF; U/M: EA; Cap_F: 0.000047; Tolerance_%: 20; VDC_V: 100; Value2: 100V; TaMin_C: -55; TaMax_C: 125; Cap_Case: 27.3x7.62mm; AEC Category: Q200
signal-integrity model Cap
simulation model Cap
footprint AVX-ST20-J10
pins: 1, 2

## RT203C227MAJ10
designator C?  ValueDisplayed: 220µF  (hidden comment: RT203C227MAJ10)
CAP, CERM, 220 µF, 25 V,+/- 20%, X7R, 1075x300mil; Manufacturer: AVX; Polarized: N; CompType: Capacitor; Value: 220uF; U/M: EA; Cap_F: 0.00022; Tolerance_%: 20; VDC_V: 25; Value2: 25V; TaMin_C: -55; TaMax_C: 125; Cap_Case: 27.3x7.62mm; AEC Category: Q200
signal-integrity model Cap
simulation model Cap
footprint AVX-ST20-J10
pins: 1, 2

## SA111E104MAR
designator C?  ValueDisplayed: 0.1µF  (hidden comment: SA111E104MAR)
CAP, CERM, 0.1 µF, 100 V,+/- 20%, Z5U, D3.05xL4.32mm; Manufacturer: AVX; Polarized: N; CompType: Capacitor; Value: 0.1uF; U/M: EA; Cap_F: 0.0000001; Tolerance_%: 20; VDC_V: 100; Value2: 100V; TaMin_C: 10; TaMax_C: 85; Cap_Case: 3.05x4.32; SizeArea_mm2: 21.35; SizeAreaWB_mm2: 45.45; SizeX_mm: 7; SizeY_mm: 3.05; AEC Category: Q200; Green_Lifecycle: Active; Green_REACh: Passed
signal-integrity model Cap
simulation model Cap
footprint SA11
pins: 1, 2

## SR1812X7R475KENT9#M123
designator C?  ValueDisplayed: 4.7µF  (hidden comment: SR1812X7R475KENT9#M123)
CAP, CERM, 4.7 µF, 10 V,+/- 10%, X7R, 1812; Manufacturer: Presidio Components; Polarized: N; CompType: Capacitor; Value: 4.7uF; U/M: EA; Cap_F: 0.0000047; Tolerance_%: 10; Value2: 10V; TaMin_C: -55; TaMax_C: 125; Cap_Case: 1812; SizeArea_mm2: 14.4; SizeAreaWB_mm2: 23.1; SizeX_mm: 4.5; SizeY_mm: 3.2; SizeZ_mm: 2.54; AEC Category: Q200
signal-integrity model Cap
simulation model Cap
footprint 1812_254
pins: 1, 2

## SV09AC105KAR
designator C?  ValueDisplayed: 1µF  (hidden comment: SV09AC105KAR)
CAP, CERM, 1 µF, 1000 V,+/- 10%, X7R, 19.6x18.3x5.08mm; Manufacturer: AVX; Polarized: N; CompType: Capacitor; Value: 1uF; U/M: EA; Cap_F: 0.000001; Tolerance_%: 10; VDC_V: 1000; Value2: 1000V; TaMin_C: -55; TaMax_C: 125; SizeArea_mm2: 99.568; SizeAreaWB_mm2: 152.928; SizeX_mm: 19.6; SizeY_mm: 5.08; SizeZ_mm: 18.3; AEC Category: Q200
signal-integrity model Cap
simulation model Cap
footprint SV09
pins: 1, 2

## SV11CC225KAR
designator C?  ValueDisplayed: 2.2µF  (hidden comment: SV11CC225KAR)
CAP, CERM, 2.2 µF, 630 V,+/- 10%, X7R, 31.8x15.2x5.08mm; Manufacturer: AVX; Polarized: N; CompType: Capacitor; Value: 2.2uF; U/M: EA; Cap_F: 0.0000022; Tolerance_%: 10; VDC_V: 630; Value2: 630V; TaMin_C: -55; TaMax_C: 125; SizeArea_mm2: 161.544; SizeAreaWB_mm2: 239.304; SizeX_mm: 31.8; SizeY_mm: 5.08; SizeZ_mm: 15.2; AEC Category: Q200
signal-integrity model Cap
simulation model Cap
footprint SV11
pins: 1, 2

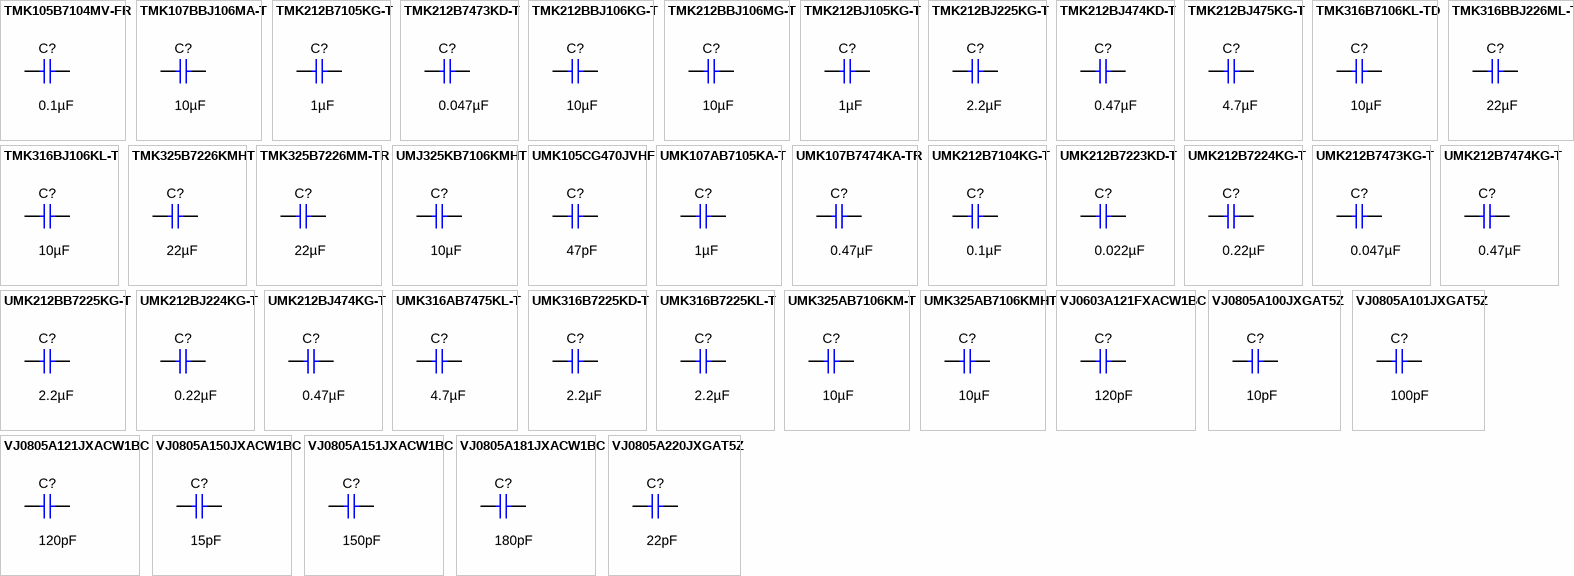
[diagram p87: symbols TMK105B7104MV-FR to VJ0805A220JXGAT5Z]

## TMK105B7104MV-FR
designator C?  ValueDisplayed: 0.1µF  (hidden comment: TMK105B7104MV-FR)
CAP, CERM, 0.1 µF, 25 V,+/- 20%, X7R, 0402; Manufacturer: Taiyo Yuden; Polarized: N; CompType: Capacitor; Value: 0.1uF; U/M: EA; Cap_F: 0.0000001; Tolerance_%: 20; VDC_V: 25; Value2: 25V; TaMin_C: -55; TaMax_C: 125; Cap_Case: 0402; SizeArea_mm2: 0.5; SizeAreaWB_mm2: 3; SizeX_mm: 1; SizeZ_mm: 0.6; AEC Category: Q200
signal-integrity model Cap
simulation model Cap
footprint 0402
footprint 0402M
footprint 0402L
footprint 0402S
pins: 1, 2

## TMK107BBJ106MA-T
designator C?  ValueDisplayed: 10µF  (hidden comment: TMK107BBJ106MA-T)
CAP, CERM, 10 µF, 25 V,+/- 20%, X5R, 0603; Manufacturer: Taiyo Yuden; Polarized: N; CompType: Capacitor; Value: 10uF; U/M: EA; Cap_F: 0.00001; Tolerance_%: 20; VDC_V: 25; Value2: 25V; TaMin_C: -55; TaMax_C: 85; Cap_Case: 0603; SizeArea_mm2: 1.28; SizeAreaWB_mm2: 4.68; SizeX_mm: 1.6; SizeY_mm: 0.8; SizeZ_mm: 1; AEC Category: Q200
signal-integrity model Cap
simulation model Cap
footprint 0603
footprint 0603M
footprint 0603L
footprint 0603_HV
footprint 0603S
pins: 1, 2

## TMK212B7105KG-T
designator C?  ValueDisplayed: 1µF  (hidden comment: TMK212B7105KG-T)
CAP, CERM, 1 µF, 25 V,+/- 10%, X7R, 0805; Manufacturer: Taiyo Yuden; Polarized: N; CompType: Capacitor; Value: 1uF; U/M: EA; Cap_F: 0.000001; Tolerance_%: 10; VDC_V: 25; Value2: 25V; TaMin_C: -55; TaMax_C: 125; Cap_Case: 0805; SizeArea_mm2: 2.5; SizeAreaWB_mm2: 6.75; SizeX_mm: 2; SizeY_mm: 1.25; SizeZ_mm: 1.45; AEC Category: Q200
signal-integrity model Cap
simulation model Cap
footprint 0805_HV
footprint 0805_HV1
footprint 0805
footprint 0805M
footprint 0805L
pins: 1, 2

## TMK212B7473KD-T
designator C?  ValueDisplayed: 0.047µF  (hidden comment: TMK212B7473KD-T)
CAP, CERM, 0.047 µF, 25 V,+/- 10%, X7R, 0805; Manufacturer: Taiyo Yuden; Polarized: N; CompType: Capacitor; Value: 0.047uF; U/M: EA; Cap_F: 0.000000047; Tolerance_%: 10; VDC_V: 25; Value2: 25V; TaMin_C: -55; TaMax_C: 125; Cap_Case: 0805; SizeArea_mm2: 2.5; SizeAreaWB_mm2: 6.75; SizeX_mm: 2; SizeY_mm: 1.25; SizeZ_mm: 1.45; AEC Category: Q200
signal-integrity model Cap
simulation model Cap
footprint 0805_HV
footprint 0805_HV1
footprint 0805
footprint 0805M
footprint 0805L
pins: 1, 2

## TMK212BBJ106KG-T
designator C?  ValueDisplayed: 10µF  (hidden comment: TMK212BBJ106KG-T)
CAP, CERM, 10 µF, 25 V,+/- 10%, X5R, 0805; Manufacturer: Taiyo Yuden; Polarized: N; CompType: Capacitor; Value: 10uF; U/M: EA; Cap_F: 0.00001; Tolerance_%: 10; VDC_V: 25; Value2: 25V; TaMin_C: -55; TaMax_C: 85; Cap_Case: 0805; SizeArea_mm2: 2.5; SizeAreaWB_mm2: 6.75; SizeX_mm: 2; SizeY_mm: 1.25; SizeZ_mm: 1.45; AEC Category: Q200; Green_Lifecycle: Not Set; Green_REACh: Incomplete
signal-integrity model Cap
simulation model Cap
footprint 0805_HV
footprint 0805_HV1
footprint 0805
footprint 0805M
footprint 0805L
pins: 1, 2

## TMK212BBJ106MG-T
designator C?  ValueDisplayed: 10µF  (hidden comment: TMK212BBJ106MG-T)
CAP, CERM, 10 µF, 25 V,+/- 20%, X5R, 0805; Manufacturer: Taiyo Yuden; Polarized: N; CompType: Capacitor; Value: 10uF; U/M: EA; Cap_F: 0.00001; Tolerance_%: 20; VDC_V: 25; Value2: 25V; TaMin_C: -55; TaMax_C: 85; Cap_Case: 0805; SizeArea_mm2: 2.5; SizeAreaWB_mm2: 6.75; SizeX_mm: 2; SizeY_mm: 1.25; SizeZ_mm: 1.45; AEC Category: Q200
signal-integrity model Cap
simulation model Cap
footprint 0805_HV
footprint 0805_HV1
footprint 0805
footprint 0805M
footprint 0805L
pins: 1, 2

## TMK212BJ105KG-T
designator C?  ValueDisplayed: 1µF  (hidden comment: TMK212BJ105KG-T)
CAP, CERM, 1 µF, 20 V,+/- 10%, X5R, 0805; Manufacturer: Taiyo Yuden; Polarized: N; CompType: Capacitor; Value: 1uF; U/M: EA; Cap_F: 0.000001; Tolerance_%: 10; VDC_V: 20; Value2: 20V; TaMin_C: -55; TaMax_C: 85; Cap_Case: 0805; SizeArea_mm2: 2.5; SizeAreaWB_mm2: 6.75; SizeX_mm: 2; SizeY_mm: 1.25; SizeZ_mm: 1.45; AEC Category: Q200
signal-integrity model Cap
simulation model Cap
footprint 0805_HV
footprint 0805_HV1
footprint 0805
footprint 0805M
footprint 0805L
pins: 1, 2

## TMK212BJ225KG-T
designator C?  ValueDisplayed: 2.2µF  (hidden comment: TMK212BJ225KG-T)
CAP, CERM, 2.2 µF, 20 V,+/- 10%, X5R, 0805; Manufacturer: Taiyo Yuden; Polarized: N; CompType: Capacitor; Value: 2.2uF; U/M: EA; Cap_F: 0.0000022; Tolerance_%: 10; VDC_V: 20; Value2: 20V; TaMin_C: -55; TaMax_C: 85; Cap_Case: 0805; SizeArea_mm2: 2.5; SizeAreaWB_mm2: 6.75; SizeX_mm: 2; SizeY_mm: 1.25; SizeZ_mm: 1.45; AEC Category: Q200; Green_Lifecycle: Not Set; Green_REACh: Incomplete
signal-integrity model Cap
simulation model Cap
footprint 0805_HV
footprint 0805_HV1
footprint 0805
footprint 0805M
footprint 0805L
pins: 1, 2

## TMK212BJ474KD-T
designator C?  ValueDisplayed: 0.47µF  (hidden comment: TMK212BJ474KD-T)
CAP, CERM, 0.47 µF, 20 V,+/- 10%, X5R, 0805; Manufacturer: Taiyo Yuden; Polarized: N; CompType: Capacitor; Value: 0.47uF; U/M: EA; Cap_F: 0.00000047; Tolerance_%: 10; VDC_V: 20; Value2: 20V; TaMin_C: -55; TaMax_C: 85; Cap_Case: 0805; SizeArea_mm2: 2.5; SizeAreaWB_mm2: 6.75; SizeX_mm: 2; SizeY_mm: 1.25; SizeZ_mm: 1.45; AEC Category: Q200; Green_Lifecycle: Not Set; Green_REACh: Incomplete
signal-integrity model Cap
simulation model Cap
footprint 0805_HV
footprint 0805_HV1
footprint 0805
footprint 0805M
footprint 0805L
pins: 1, 2

## TMK212BJ475KG-T
designator C?  ValueDisplayed: 4.7µF  (hidden comment: TMK212BJ475KG-T)
CAP, CERM, 4.7 µF, 25 V,+/- 10%, X5R, 0805; Manufacturer: Taiyo Yuden; Polarized: N; CompType: Capacitor; Value: 4.7uF; U/M: EA; Cap_F: 0.0000047; Tolerance_%: 10; VDC_V: 25; Value2: 25V; TaMin_C: -55; TaMax_C: 85; Cap_Case: 0805; SizeArea_mm2: 2.5; SizeAreaWB_mm2: 6.75; SizeX_mm: 2; SizeY_mm: 1.25; SizeZ_mm: 1.45; AEC Category: Q200; Green_Lifecycle: Not Set; Green_REACh: Incomplete
signal-integrity model Cap
simulation model Cap
footprint 0805_HV
footprint 0805_HV1
footprint 0805
footprint 0805M
footprint 0805L
pins: 1, 2

## TMK316B7106KL-TD
designator C?  ValueDisplayed: 10µF  (hidden comment: TMK316B7106KL-TD)
CAP, CERM, 10 µF, 25 V,+/- 10%, X7R, 1206; Manufacturer: Taiyo Yuden; Polarized: N; CompType: Capacitor; Value: 10uF; U/M: EA; Cap_F: 0.00001; Tolerance_%: 10; VDC_V: 25; Value2: 25V; TaMin_C: -55; TaMax_C: 125; Cap_Case: 1206; SizeArea_mm2: 5.12; SizeAreaWB_mm2: 10.92; SizeX_mm: 3.2; SizeY_mm: 1.6; SizeZ_mm: 1.9; AEC Category: Q200; Green_Lifecycle: Not Set; Green_REACh: Incomplete
signal-integrity model Cap
simulation model Cap
footprint 1206_190
footprint 1206_190M
footprint 1206_190L
pins: 1, 2

## TMK316BBJ226ML-T
designator C?  ValueDisplayed: 22µF  (hidden comment: TMK316BBJ226ML-T)
CAP, CERM, 22 µF, 25 V,+/- 20%, X5R, 1206; Manufacturer: Taiyo Yuden; Polarized: N; CompType: Capacitor; Value: 22uF; U/M: EA; Cap_F: 0.000022; Tolerance_%: 20; VDC_V: 25; Value2: 25V; TaMin_C: -55; TaMax_C: 85; Cap_Case: 1206; SizeArea_mm2: 5.12; SizeAreaWB_mm2: 10.92; SizeX_mm: 3.2; SizeY_mm: 1.6; SizeZ_mm: 1.9; AEC Category: Q200
signal-integrity model Cap
simulation model Cap
footprint 1206_190
footprint 1206_190M
footprint 1206_190L
pins: 1, 2

## TMK316BJ106KL-T
designator C?  ValueDisplayed: 10µF  (hidden comment: TMK316BJ106KL-T)
CAP, CERM, 10 µF, 25 V,+/- 10%, X5R, 1206; Manufacturer: Taiyo Yuden; Polarized: N; CompType: Capacitor; Value: 10uF; U/M: EA; Cap_F: 0.00001; Tolerance_%: 10; VDC_V: 25; Value2: 25V; TaMin_C: -55; TaMax_C: 85; Cap_Case: 1206; SizeArea_mm2: 5.12; SizeAreaWB_mm2: 10.92; SizeX_mm: 3.2; SizeY_mm: 1.6; SizeZ_mm: 1.35; AEC Category: Q200; Green_Lifecycle: Active; Green_REACh: Passed
signal-integrity model Cap
simulation model Cap
footprint 1206
footprint 1206M
footprint 1206L
pins: 1, 2

## TMK325B7226KMHT
designator C?  ValueDisplayed: 22µF  (hidden comment: TMK325B7226KMHT)
CAP, CERM, 22 µF, 25 V,+/- 10%, X7R, AEC-Q200 Grade 1, 1210; Manufacturer: Taiyo Yuden; Polarized: N; CompType: Capacitor; Value: 22uF; U/M: EA; Cap_F: 0.000022; Tolerance_%: 10; VDC_V: 25; Value2: 25V; TaMin_C: -55; TaMax_C: 125; Cap_Case: 1210; SizeArea_mm2: 8; SizeAreaWB_mm2: 14.7; SizeX_mm: 3.2; SizeY_mm: 2.5; SizeZ_mm: 2.7; AEC Category: Q200; AEC Qualified: Y; AEC Grade: 1
signal-integrity model Cap
simulation model Cap
footprint 1210_270
footprint 1210_270M
footprint 1210_270L
pins: 1, 2

## TMK325B7226MM-TR
designator C?  ValueDisplayed: 22µF  (hidden comment: TMK325B7226MM-TR)
CAP, CERM, 22 µF, 25 V,+/- 20%, X7R, 1210; Manufacturer: Taiyo Yuden; Polarized: N; CompType: Capacitor; Value: 22uF; U/M: EA; Cap_F: 0.000022; Tolerance_%: 20; VDC_V: 25; Value2: 25V; TaMin_C: -55; TaMax_C: 125; Cap_Case: 1210; SizeArea_mm2: 8; SizeAreaWB_mm2: 14.7; SizeX_mm: 3.2; SizeY_mm: 2.5; SizeZ_mm: 2.7; AEC Category: Q200; Green_Lifecycle: Active; Green_REACh: Passed
signal-integrity model Cap
simulation model Cap
footprint 1210_270
footprint 1210_270M
footprint 1210_270L
pins: 1, 2

## UMJ325KB7106KMHT
designator C?  ValueDisplayed: 10µF  (hidden comment: UMJ325KB7106KMHT)
CAP, CERM, 10 µF, 50 V,+/- 10%, X7R, AEC-Q200 Grade 1, 1210; Manufacturer: Taiyo Yuden; Polarized: N; CompType: Capacitor; Value: 10uF; U/M: EA; Cap_F: 0.00001; Tolerance_%: 10; VDC_V: 50; Value2: 50V; TaMin_C: -55; TaMax_C: 125; Cap_Case: 1210; SizeArea_mm2: 8; SizeAreaWB_mm2: 14.7; SizeX_mm: 3.2; SizeY_mm: 2.5; SizeZ_mm: 2.7; AEC Category: Q200; AEC Qualified: Y; AEC Grade: 1
signal-integrity model Cap
simulation model Cap
footprint 1210_270
footprint 1210_270M
footprint 1210_270L
pins: 1, 2

## UMK105CG470JVHF
designator C?  ValueDisplayed: 47pF  (hidden comment: UMK105CG470JVHF)
CAP, CERM, 47 pF, 50 V,+/- 5%, C0G/NP0, 0402; Manufacturer: Taiyo Yuden; Polarized: N; CompType: Capacitor; Value: 47pF; U/M: EA; Cap_F: 0.000000000047; Tolerance_%: 5; VDC_V: 50; Value2: 50V; TaMin_C: -55; TaMax_C: 125; Cap_Case: 0402; SizeArea_mm2: 0.5; SizeAreaWB_mm2: 3; SizeX_mm: 1; SizeZ_mm: 0.6; AEC Category: Q200
signal-integrity model Cap
simulation model Cap
footprint 0402
footprint 0402M
footprint 0402L
footprint 0402S
pins: 1, 2

## UMK107AB7105KA-T
designator C?  ValueDisplayed: 1µF  (hidden comment: UMK107AB7105KA-T)
CAP, CERM, 1 µF, 50 V,+/- 10%, X7R, 0603; Manufacturer: Taiyo Yuden; Polarized: N; CompType: Capacitor; Value: 1uF; U/M: EA; Cap_F: 0.000001; Tolerance_%: 10; VDC_V: 50; Value2: 50V; TaMin_C: -55; TaMax_C: 125; Cap_Case: 0603; SizeArea_mm2: 1.28; SizeAreaWB_mm2: 4.68; SizeX_mm: 1.6; SizeY_mm: 0.8; SizeZ_mm: 1; AEC Category: Q200; Green_Lifecycle: Active; Green_REACh: Passed
signal-integrity model Cap
simulation model Cap
footprint 0603
footprint 0603M
footprint 0603L
footprint 0603_HV
footprint 0603S
pins: 1, 2

## UMK107B7474KA-TR
designator C?  ValueDisplayed: 0.47µF  (hidden comment: UMK107B7474KA-TR)
CAP, CERM, 0.47 µF, 50 V,+/- 10%, X7R, 0603; Manufacturer: Taiyo Yuden; Polarized: N; CompType: Capacitor; Value: 0.47uF; U/M: EA; Cap_F: 0.00000047; Tolerance_%: 10; VDC_V: 50; Value2: 50V; TaMin_C: -55; TaMax_C: 125; Cap_Case: 0603; SizeArea_mm2: 1.28; SizeAreaWB_mm2: 4.68; SizeX_mm: 1.6; SizeY_mm: 0.8; SizeZ_mm: 1; AEC Category: Q200
signal-integrity model Cap
simulation model Cap
footprint 0603
footprint 0603M
footprint 0603L
footprint 0603_HV
footprint 0603S
pins: 1, 2

## UMK212B7104KG-T
designator C?  ValueDisplayed: 0.1µF  (hidden comment: UMK212B7104KG-T)
CAP, CERM, 0.1 µF, 50 V,+/- 10%, X7R, 0805; Manufacturer: Taiyo Yuden; Polarized: N; CompType: Capacitor; Value: 0.1uF; U/M: EA; Cap_F: 0.0000001; Tolerance_%: 10; VDC_V: 50; Value2: 50V; TaMin_C: -55; TaMax_C: 125; Cap_Case: 0805; SizeArea_mm2: 2.5; SizeAreaWB_mm2: 6.75; SizeX_mm: 2; SizeY_mm: 1.25; SizeZ_mm: 1.45; AEC Category: Q200
signal-integrity model Cap
simulation model Cap
footprint 0805_HV
footprint 0805_HV1
footprint 0805
footprint 0805M
footprint 0805L
pins: 1, 2

## UMK212B7223KD-T
designator C?  ValueDisplayed: 0.022µF  (hidden comment: UMK212B7223KD-T)
CAP, CERM, 0.022 µF, 50 V,+/- 10%, X7R, 0805; Manufacturer: Taiyo Yuden; Polarized: N; CompType: Capacitor; Value: 0.022uF; U/M: EA; Cap_F: 0.000000022; Tolerance_%: 10; VDC_V: 50; Value2: 50V; TaMin_C: -55; TaMax_C: 125; Cap_Case: 0805; SizeArea_mm2: 2.5; SizeAreaWB_mm2: 6.75; SizeX_mm: 2; SizeY_mm: 1.25; SizeZ_mm: 1.45; AEC Category: Q200
signal-integrity model Cap
simulation model Cap
footprint 0805_HV
footprint 0805_HV1
footprint 0805
footprint 0805M
footprint 0805L
pins: 1, 2

## UMK212B7224KG-T
designator C?  ValueDisplayed: 0.22µF  (hidden comment: UMK212B7224KG-T)
CAP, CERM, 0.22 µF, 50 V,+/- 10%, X7R, 0805; Manufacturer: Taiyo Yuden; Polarized: N; CompType: Capacitor; Value: 0.22uF; U/M: EA; Cap_F: 0.00000022; Tolerance_%: 10; VDC_V: 50; Value2: 50V; TaMin_C: -55; TaMax_C: 125; Cap_Case: 0805; SizeArea_mm2: 2.5; SizeAreaWB_mm2: 6.75; SizeX_mm: 2; SizeY_mm: 1.25; SizeZ_mm: 1.45; AEC Category: Q200
signal-integrity model Cap
simulation model Cap
footprint 0805_HV
footprint 0805_HV1
footprint 0805
footprint 0805M
footprint 0805L
pins: 1, 2

## UMK212B7473KG-T
designator C?  ValueDisplayed: 0.047µF  (hidden comment: UMK212B7473KG-T)
CAP, CERM, 0.047 µF, 50 V,+/- 10%, X7R, 0805; Manufacturer: Taiyo Yuden; Polarized: N; CompType: Capacitor; Value: 0.047uF; U/M: EA; Cap_F: 0.000000047; Tolerance_%: 10; VDC_V: 50; Value2: 50V; TaMin_C: -55; TaMax_C: 125; Cap_Case: 0805; SizeArea_mm2: 2.5; SizeAreaWB_mm2: 6.75; SizeX_mm: 2; SizeY_mm: 1.25; SizeZ_mm: 1.45; AEC Category: Q200
signal-integrity model Cap
simulation model Cap
footprint 0805_HV
footprint 0805_HV1
footprint 0805
footprint 0805M
footprint 0805L
pins: 1, 2

## UMK212B7474KG-T
designator C?  ValueDisplayed: 0.47µF  (hidden comment: UMK212B7474KG-T)
CAP, CERM, 0.47 µF, 50 V,+/- 10%, X7R, 0805; Manufacturer: Taiyo Yuden; Polarized: N; CompType: Capacitor; Value: 0.47uF; U/M: EA; Cap_F: 0.00000047; Tolerance_%: 10; VDC_V: 50; Value2: 50V; TaMin_C: -55; TaMax_C: 125; Cap_Case: 0805; SizeArea_mm2: 2.5; SizeAreaWB_mm2: 6.75; SizeX_mm: 2; SizeY_mm: 1.25; SizeZ_mm: 1.45; AEC Category: Q200; Green_Lifecycle: Active; Green_REACh: Passed
signal-integrity model Cap
simulation model Cap
footprint 0805_HV
footprint 0805_HV1
footprint 0805
footprint 0805M
footprint 0805L
pins: 1, 2

## UMK212BB7225KG-T
designator C?  ValueDisplayed: 2.2µF  (hidden comment: UMK212BB7225KG-T)
CAP, CERM, 2.2 µF, 50 V,+/- 10%, X7R, 0805; Manufacturer: Taiyo Yuden; Polarized: N; CompType: Capacitor; Value: 2.2uF; U/M: EA; Cap_F: 0.0000022; Tolerance_%: 10; VDC_V: 50; Value2: 50V; TaMin_C: -55; TaMax_C: 125; Cap_Case: 0805; SizeArea_mm2: 2.5; SizeAreaWB_mm2: 6.75; SizeX_mm: 2; SizeY_mm: 1.25; SizeZ_mm: 1.45; AEC Category: Q200; Green_Lifecycle: Active; Green_REACh: Passed
signal-integrity model Cap
simulation model Cap
footprint 0805_HV
footprint 0805_HV1
footprint 0805
footprint 0805M
footprint 0805L
pins: 1, 2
